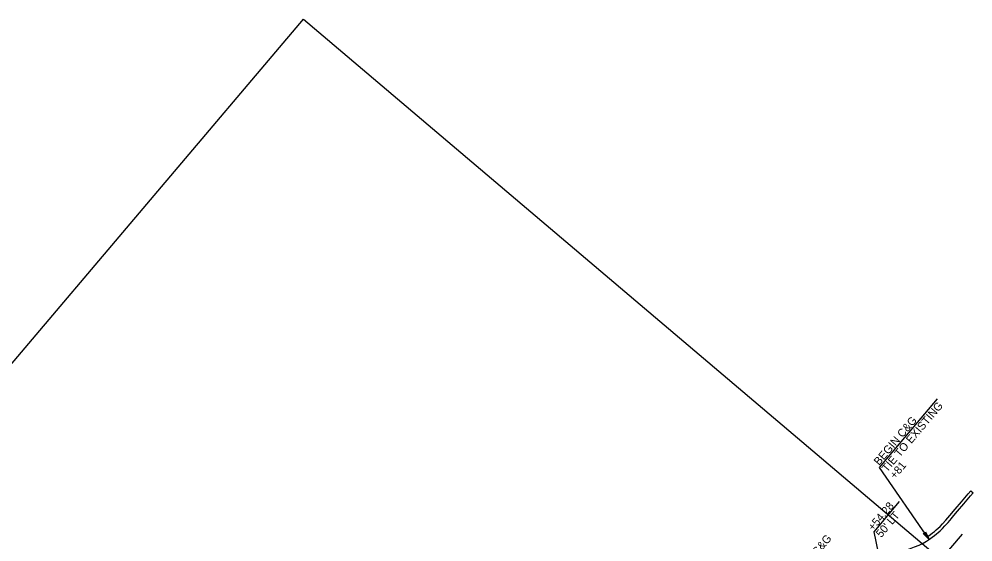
# Model space of a CAD drawing. Extents: x 1761082 to 1764358, y 421907 to 425434.
# Drawn here: x 1763418 to 1764013, y 425108 to 425434 of the extents above; entities that cross this region are included whole.
import ezdxf

# ---------------------------------------------------------------- set-up
doc = ezdxf.new("R2010")
doc.units = 0
for name, color, linetype in [('MARK LEFT TURN ARROW CELL', 7, 'Continuous'), ('Prop Mkg Skp Wht', 7, 'Continuous'), ('Prop Mkg Solid White Multiple Diagonals V8i', 7, 'Continuous'), ('Prop Mkg Solid Yel Skip LT', 7, 'Continuous'), ('Prop Mkg Solid Yel Skip RT', 7, 'Continuous'), ('Prop Mkg Solid Yellow Edge Line', 7, 'Continuous'), ('Prop Mkg Solid Yellow Lane Line', 7, 'Continuous')]:
    doc.layers.add(name, color=color, linetype=linetype)

msp = doc.modelspace()

# ---------------------------------------------------------------- linework, layer by layer
at = {"layer": 'MARK LEFT TURN ARROW CELL'}
for p, q in [((1764012.01, 425139.54), (1764013.54, 425138.24)), ((1763984.91, 425110.82), (1763985.99, 425109.16))]:
    msp.add_line(p, q, dxfattribs=at)
for points in [[(1763998.91, 425124.07), (1763998.93, 425124.09), (1764002.31, 425128.04), (1764006.23, 425132.65), (1764010.41, 425137.63), (1764012.01, 425139.54)], [(1763984.91, 425110.82), (1763986.85, 425112.2), (1763988.17, 425113.21), (1763989.35, 425114.15), (1763990.52, 425115.09), (1763991.7, 425116.11), (1763992.96, 425117.32), (1763994.47, 425118.92), (1763996.39, 425121.11), (1763998.93, 425124.09)]]:
    msp.add_lwpolyline(points, dxfattribs=at)
at = {"layer": 'Prop Mkg Skp Wht'}
for points in [[(1763999.96, 425122.22), (1764000.45, 425122.79), (1764003.83, 425126.74), (1764007.75, 425131.36), (1764011.94, 425136.35), (1764013.54, 425138.24)], [(1763954.47, 425100.88), (1763957.84, 425100.88), (1763961.6, 425101.07), (1763964.96, 425101.43), (1763968.04, 425101.94), (1763970.97, 425102.56), (1763973.88, 425103.38), (1763976.91, 425104.46), (1763979.79, 425105.68), (1763982.26, 425106.9), (1763984.41, 425108.14), (1763986.36, 425109.4), (1763988.04, 425110.59), (1763989.4, 425111.63), (1763990.6, 425112.59), (1763991.8, 425113.56), (1763993.05, 425114.63), (1763994.38, 425115.91), (1763995.95, 425117.58), (1763997.9, 425119.8), (1763999.96, 425122.22)]]:
    msp.add_lwpolyline(points, dxfattribs=at)
at = {"layer": 'Prop Mkg Solid White Multiple Diagonals V8i'}
for p, q in [((1761203.63, 422611.03), (1763595.27, 425434.16)), ((1763595.27, 425434.16), (1764358.27, 424787.77))]:
    msp.add_line(p, q, dxfattribs=at)
at = {"layer": 'Prop Mkg Solid Yel Skip RT'}
for points in [[(1763985.99, 425109.16), (1763955.01, 425154.03), (1763991.34, 425196.91)], [(1763954.47, 425100.88), (1763951.69, 425113.96), (1763967.61, 425132.75)]]:
    msp.add_lwpolyline(points, dxfattribs=at)
at = {"layer": 'Prop Mkg Solid Yellow Edge Line'}
msp.add_line((1763947.38, 425043.11), (1764006.91, 425112.48), dxfattribs=at)
at = {"layer": 'Prop Mkg Solid Yellow Lane Line'}
msp.add_lwpolyline([(1763983.81, 425113.86), (1763985.99, 425109.16), (1763982.33, 425112.87), (1763983.44, 425112.85)], close=True, dxfattribs=at)

# ---------------------------------------------------------------- texts
at = {"layer": 'Prop Mkg Solid Yel Skip LT'}
for s, p in [('TIE TO EXISTING', (1763959.8, 425150.8)), ('BEGIN C&G', (1763954.8, 425155.03)), ('+81', (1763964.8, 425146.56)), ('+54.28', (1763951.12, 425114.16)), ("50' LT", (1763956.13, 425109.92)), ('END C&G', (1763905.82, 425086.36))]:
    msp.add_text(s, height=5, rotation=49.7301, dxfattribs=at).set_placement(p)

doc.saveas('drawing.dxf')
